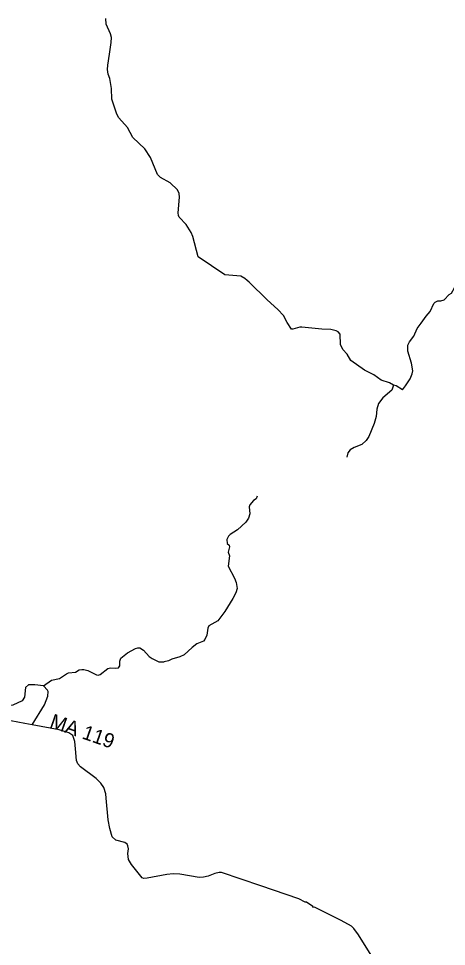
# Model space of a CAD drawing. Extents: x 332 to 501, y 9447 to 9559.
# Drawn here: x 448.76 to 460.06, y 9533.34 to 9557.86 of the extents above; entities that cross this region are included whole.
import ezdxf

# ---------------------------------------------------------------- set-up
doc = ezdxf.new("R2010")
doc.units = 0
for name, color, linetype in [('Level 31', 7, 'Continuous'), ('Level 5', 7, 'Continuous'), ('Level 6', 7, 'Continuous'), ('Level 7', 7, 'Continuous')]:
    doc.layers.add(name, color=color, linetype=linetype)

msp = doc.modelspace()

# ---------------------------------------------------------------- linework, layer by layer
at = {"layer": 'Level 5'}
for points in [[(450.4287, 9540.663), (450.4817, 9540.6643), (450.5903, 9540.6352), (450.8218, 9540.5162), (450.8656, 9540.5131), (450.9172, 9540.5288), (451.1206, 9540.6883), (451.191, 9540.7071), (451.3333, 9540.693), (451.398, 9540.7047), (451.4356, 9540.7595), (451.4309, 9540.8801), (451.4637, 9540.9571), (451.6404, 9541.1022), (451.8523, 9541.217), (451.9086, 9541.2326), (451.9618, 9541.2295), (452.0603, 9541.17), (452.2121, 9541.0013), (452.2866, 9540.9533), (452.4658, 9540.8662), (452.602, 9540.8677)], [(449.4204, 9540.23), (449.6336, 9540.379), (449.8381, 9540.422), (450.0249, 9540.5507), (450.0779, 9540.5709), (450.2621, 9540.5948), (450.3618, 9540.6492), (450.4287, 9540.663)], [(449.4204, 9540.23), (449.1918, 9540.2541), (449.0278, 9540.2528), (448.9486, 9540.1812), (448.922, 9539.9309), (448.8547, 9539.837), (448.6138, 9539.7165), (448.1107, 9539.6687)], [(449.5409, 9540.0814), (449.5252, 9540.1174), (449.4204, 9540.23)], [(449.1216, 9539.2007), (449.4423, 9539.731), (449.5315, 9539.9594), (449.5409, 9540.0814)], [(448.9279, 9539.2381), (448.5551, 9539.3031)], [(449.1216, 9539.2007), (448.9279, 9539.2381)], [(449.835, 9539.0667), (449.1216, 9539.2007)], [(450.2648, 9538.5689), (450.2445, 9538.7585), (450.1977, 9538.92), (450.088, 9538.9919), (449.835, 9539.0667)], [(455.1576, 9534.944), (454.1167, 9535.299), (454.0561, 9535.3015), (453.9438, 9535.275), (453.7696, 9535.198), (453.6472, 9535.1702), (453.5311, 9535.1639), (453.0186, 9535.2548), (452.847, 9535.2624), (452.6753, 9535.2472), (452.1604, 9535.1475), (452.072, 9535.1412), (452.0266, 9535.1601), (451.7426, 9535.5097), (451.6628, 9535.6395), (451.6426, 9535.8007), (451.6598, 9535.9212), (451.6504, 9536.0056), (451.6269, 9536.0463), (451.5706, 9536.0901), (451.3324, 9536.156), (451.2365, 9536.2367), (451.1683, 9536.4614), (451.1267, 9536.6911), (451.0787, 9537.2616), (451.0623, 9537.3777), (451.0105, 9537.5468), (450.9361, 9537.6554), (450.8073, 9537.7816), (450.3968, 9538.0855), (450.3264, 9538.1668), (450.2951, 9538.256), (450.2648, 9538.5689)], [(458.6226, 9531.667), (458.562, 9531.8799), (458.4521, 9532.3956), (458.3895, 9532.5645), (458.2856, 9532.7634), (457.7328, 9533.6494), (457.6141, 9533.8185), (457.5535, 9533.8778), (457.2751, 9534.0311), (456.5716, 9534.3776), (456.5464, 9534.3763), (456.5299, 9534.4016), (456.3608, 9534.5127), (456.3293, 9534.5139), (456.1614, 9534.6048), (455.1576, 9534.944)]]:
    msp.add_lwpolyline(points, dxfattribs=at)
at = {"layer": 'Level 6'}
for points in [[(451.1646, 9556.9215), (451.2103, 9557.2247), (451.2113, 9557.3627), (451.1875, 9557.459), (451.0723, 9557.7133), (451.0657, 9557.8594)], [(452.9873, 9552.6521), (452.9707, 9552.7266), (453.0114, 9553.141), (452.9985, 9553.2403), (452.9568, 9553.3317), (452.7603, 9553.5164), (452.5092, 9553.6615), (452.4307, 9553.737), (452.2422, 9554.1909), (452.0924, 9554.4214), (451.7807, 9554.7164), (451.6349, 9554.9796), (451.4056, 9555.2399), (451.358, 9555.3363), (451.2242, 9555.733), (451.2153, 9556.012), (451.1677, 9556.2732), (451.125, 9556.3884), (451.1111, 9556.5116), (451.119, 9556.6278), (451.1646, 9556.9215)], [(453.5063, 9551.5672), (453.3651, 9552.0987), (453.3165, 9552.2078), (453.1827, 9552.4148), (453.0016, 9552.6097), (452.9873, 9552.6521)], [(459.3925, 9549.8137), (459.5217, 9549.9976), (459.6289, 9550.1168), (459.7281, 9550.3353), (459.7599, 9550.3701), (459.8294, 9550.3989), (459.9098, 9550.4009), (459.9981, 9550.4297), (460.1311, 9550.5678), (460.1905, 9550.6038), (460.2659, 9550.7448), (460.3463, 9550.9881), (460.4039, 9551.2394), (460.4198, 9551.4618), (460.518, 9551.6346), (460.5279, 9551.8462), (460.5835, 9552.311), (460.5795, 9552.4034), (460.5329, 9552.5087), (460.5428, 9552.5931)], [(454.7951, 9550.9343), (454.7374, 9550.9919), (454.6324, 9551.0518), (454.2089, 9551.0925), (453.5063, 9551.5672)], [(455.3243, 9550.427), (454.8459, 9550.8948), (454.7951, 9550.9343)], [(458.6565, 9548.1775), (458.5502, 9548.2328), (458.3334, 9548.3068), (458.1413, 9548.4474), (457.8927, 9548.5711), (457.5312, 9548.8269), (457.4397, 9548.9902), (457.3211, 9549.1144), (457.2612, 9549.2505), (457.2556, 9549.5222), (457.1968, 9549.5855), (457.1437, 9549.6126), (457.0059, 9549.6431), (456.7652, 9549.6527), (456.2353, 9549.7075), (456.1867, 9549.7097), (456.0013, 9549.6538), (455.9652, 9549.6572), (455.8511, 9549.8255), (455.7539, 9550.017), (455.6059, 9550.1741), (455.3243, 9550.427)], [(458.9728, 9548.1543), (459.0992, 9548.3416), (459.1534, 9548.4703), (459.1693, 9548.5562), (459.1376, 9548.755), (459.0354, 9549.0728), (459.0373, 9549.2327), (459.079, 9549.3171), (459.1932, 9549.4661), (459.2875, 9549.6727), (459.3925, 9549.8137)], [(458.6565, 9548.1775), (458.6113, 9548.0436), (458.3785, 9547.842), (458.261, 9547.6873), (458.218, 9547.5364), (458.2011, 9547.3438)], [(458.8971, 9548.0538), (458.7266, 9548.1538), (458.6565, 9548.1775)], [(458.8971, 9548.0538), (458.9728, 9548.1543)], [(455.0648, 9545.2371), (455.0309, 9545.1705), (454.9609, 9545.1298), (454.8626, 9545.0146), (454.8479, 9544.9615), (454.8682, 9544.7763), (454.8298, 9544.6572), (454.7598, 9544.5522), (454.5383, 9544.3495), (454.3463, 9544.2258), (454.3011, 9544.1807), (454.2559, 9544.0971), (454.2683, 9543.9904), (454.3191, 9543.943), (454.3304, 9543.9023), (454.2943, 9543.7572), (454.3281, 9543.6613), (454.2988, 9543.393), (454.4626, 9543.074), (454.5021, 9542.9622), (454.5303, 9542.7979), (454.4987, 9542.6861), (454.4147, 9542.535)], [(454.4147, 9542.535), (454.2073, 9542.1972), (454.0244, 9541.9494), (453.7815, 9541.811), (453.7556, 9541.7534), (453.7285, 9541.566), (453.6788, 9541.4503), (453.6449, 9541.4107), (453.4676, 9541.3373), (453.3434, 9541.2453), (453.1299, 9541.0483), (453.0204, 9540.9975), (452.808, 9540.9382), (452.7165, 9540.8885), (452.602, 9540.8677)]]:
    msp.add_lwpolyline(points, dxfattribs=at)
at = {"layer": 'Level 7'}
msp.add_lwpolyline([(458.2011, 9547.3438), (458.1506, 9547.1579), (458.0092, 9546.8172), (457.9385, 9546.7074), (457.8199, 9546.6038), (457.6192, 9546.5282), (457.5195, 9546.4625), (457.4538, 9546.3843), (457.4248, 9546.2744)], dxfattribs=at)

# ---------------------------------------------------------------- texts
at = {"layer": 'Level 31'}
msp.add_text('MA 119', height=0.38, rotation=340.72471, dxfattribs=at).set_placement((449.5602, 9539.1429))

doc.saveas('drawing.dxf')
